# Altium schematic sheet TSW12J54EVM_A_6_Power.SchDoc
size 431 x 279 mm; Date: Not shown in title block; ApprovedBy: Not shown in title block; CheckedBy: Not shown in title block; Author: Not shown in title block; CompanyName: Not shown in title block; Engineer: Not shown in title block; Organization: Not shown in title block; Address1: Not shown in title block; Address2: Not shown in title block; Address3: Not shown in title block; Address4: Not shown in title block; DocumentNumber: 6; Revision: Use project parameter SCH_Rev; SheetNumber: 6; SheetTotal: 8; PageSetup: Record=PageOptions¦CenterHorizontal=True¦CenterVertical=True¦PrintScale=1.00¦XCorrection=1.00¦YCorrection=1.00¦PrintKind=0¦BorderSize=5000000¦LeftOffset=0¦BottomOffset=0¦Orientation=2¦PaperLength=1000¦PaperWidth=1000¦Scale=100¦PaperSource=15¦PrintQuality=600¦MediaType=1¦DitherType=10¦PaperKind=Letter¦PrintScaleMode=1
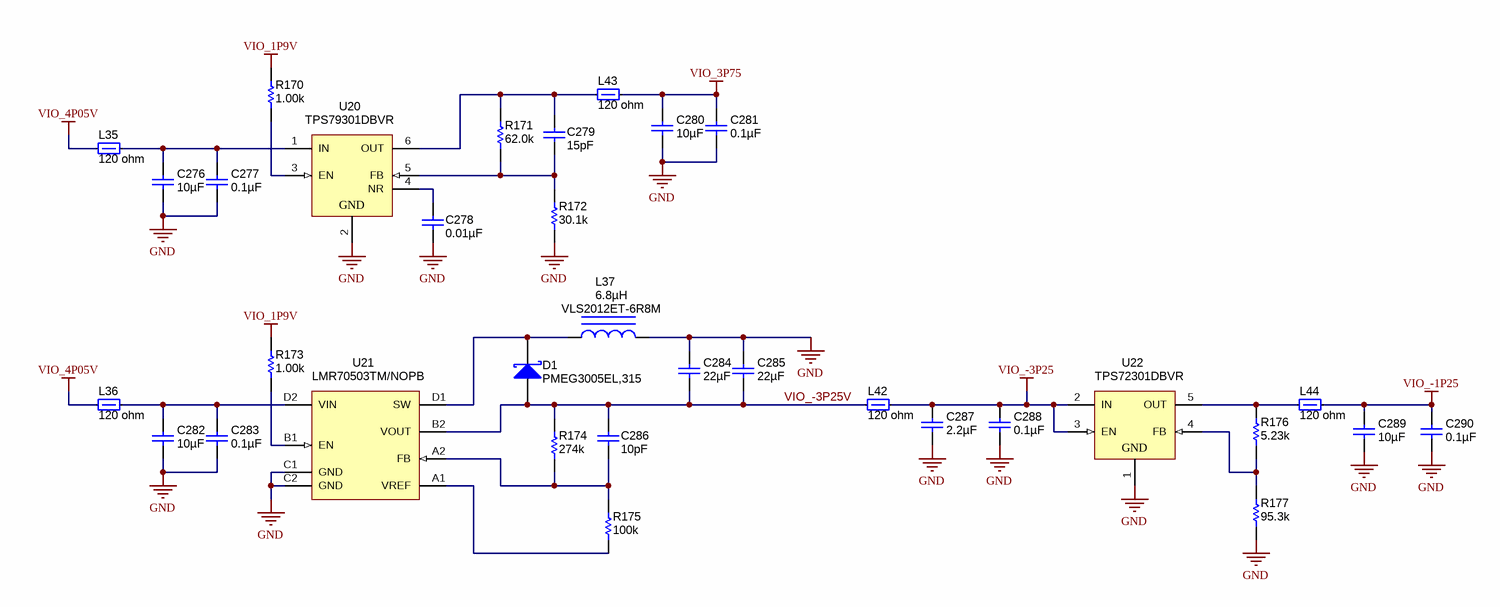
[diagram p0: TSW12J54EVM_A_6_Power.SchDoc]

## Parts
C276  ValueDisplayed: 10µF  [0603L]  (hidden comment: C1608X5R1A106M)
C277  ValueDisplayed: 0.1µF  [0603L]  (hidden comment: 06033C104JAT2A)
C278  ValueDisplayed: 0.01µF  [0603L]  (hidden comment: 06031C103MAT2A)
C279  ValueDisplayed: 15pF  [0603L]  (hidden comment: C0603C150J5GACTU)
C280  ValueDisplayed: 10µF  [0603L]  (hidden comment: C1608X5R1A106M)
C281  ValueDisplayed: 0.1µF  [0603L]  (hidden comment: 06033C104JAT2A)
C282  ValueDisplayed: 10µF  [0603L]  (hidden comment: C1608X5R1A106M)
C283  ValueDisplayed: 0.1µF  [0603L]  (hidden comment: 06033C104JAT2A)
C284  ValueDisplayed: 22µF  [0603L]  (hidden comment: C1608X5R0J226M080AC)
C285  ValueDisplayed: 22µF  [0603L]  (hidden comment: C1608X5R0J226M080AC)
C286  ValueDisplayed: 10pF  [0402L]  (hidden comment: GRM1555C1H100JA01D)
C287  ValueDisplayed: 2.2µF  [0603L]  (hidden comment: GRM188R61A225KE34D)
C288  ValueDisplayed: 0.1µF  [0603L]  (hidden comment: 06033C104JAT2A)
C289  ValueDisplayed: 10µF  [0603L]  (hidden comment: C1608X5R1A106M)
C290  ValueDisplayed: 0.1µF  [0603L]  (hidden comment: 06033C104JAT2A)
D1  PMEG3005EL,315  [SOD882]
L35  value 120 ohm  [0603]  (hidden comment: BLM18SG121TN1D)
L36  value 120 ohm  [0603]  (hidden comment: BLM18SG121TN1D)
L37  VLS2012ET-6R8M  ValueDisplayed: 6.8µH  [VLS2012]
L42  value 120 ohm  [0603]  (hidden comment: BLM18SG121TN1D)
L43  value 120 ohm  [0603]  (hidden comment: BLM18SG121TN1D)
L44  value 120 ohm  [0603]  (hidden comment: BLM18SG121TN1D)
R170  value 1.00k  [0402L]  (hidden comment: CRCW04021K00FKED)
R171  ValueDisplayed: 62.0k  [0603L]  (hidden comment: RC0603FR-0762KL)
R172  ValueDisplayed: 30.1k  [0603L]  (hidden comment: CRCW060330K1FKEA)
R173  value 1.00k  [0402L]  (hidden comment: CRCW04021K00FKED)
R174  ValueDisplayed: 274k  [0402L]  (hidden comment: CRCW0402274KFKED)
R175  ValueDisplayed: 100k  [0402L]  (hidden comment: CRCW0402100KFKED)
R176  ValueDisplayed: 5.23k  [0603L]  (hidden comment: CRCW06035K23FKEA)
R177  ValueDisplayed: 95.3k  [0603L]  (hidden comment: RC0603FR-0795K3L)
U20  TPS79301DBVR  [DBV0006A_N]
U21  LMR70503TM/NOPB  [YFX0008ADAC]
U22  TPS72301DBVR  [DBV0005A_N]

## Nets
GND: C276.2 C277.2 C278.2 C280.2 C281.2 C282.2 C283.2 C284.1 C285.1 C287.2 C288.2 C289.2 C290.2 L37.2 R172.1 R177.1 U20.2(GND) U21.C1(GND) U21.C2(GND) U22.1(GND)
VIO_1P9V: R170.1 R173.1
VIO_3P75: C280.1 C281.1 L43.2
VIO_4P05V: L35.1 L36.1
VIO_-1P25: C289.1 C290.1 L44.2
VIO_-3P25: C287.1 C288.1 L42.2 U22.2(IN) U22.3(EN)
VIO_-3P25V: C284.2 C285.2 C286.1 D1.2(A) L42.1 R174.2 U21.B2(VOUT)
NetC276_1: C276.1 C277.1 L35.2 U20.1(IN)
NetC278_1: C278.1 U20.4(NR)
NetC279_1: C279.1 L43.1 R171.1 U20.6(OUT)
NetC279_2: C279.2 R171.2 R172.2 U20.5(FB)
NetC282_1: C282.1 C283.1 L36.2 U21.D2(VIN)
NetC286_2: C286.2 R174.1 R175.2 U21.A2(FB)
NetD1_1: D1.1(K) L37.1 U21.D1(SW)
NetL44_1: L44.1 R176.2 U22.5(OUT)
NetR170_2: R170.2 U20.3(EN)
NetR173_2: R173.2 U21.B1(EN)
NetR175_1: R175.1 U21.A1(VREF)
NetR176_1: R176.1 R177.2 U22.4(FB)

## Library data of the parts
C276 C280 C282 C289 = C1608X5R1A106M: CAP, CERM, 10uF, 10V, +/-10%, C0G/NP0, 0603; Manufacturer: TDK; Polarized: N; CompType: Capacitor; U/M: EA; Cap_F: 0.00001; Tolerance_%: 10; ESR_Ohm: 0.0078; Value1: 0.0078 ohm; IRMS_A: 1.85; TaMin_C: -55; TaMax_C: 85; Cap_Case: 0603
C277 C281 C283 C288 C290 = 06033C104JAT2A: CAP, CERM, 0.1uF, 25V, +/-5%, X7R, 0603; Manufacturer: AVX; Polarized: N; CompType: Capacitor; U/M: EA; Cap_F: 0.0000001; Tolerance_%: 5; ESR_Ohm: 0.05; Value1: 0.05 ohm; VDC_V: 25; TaMin_C: -55; TaMax_C: 125; Cap_Case: 0603
C278 = 06031C103MAT2A: CAP, CERM, 0.01uF, 100V, +/-20%, X7R, 0603; Manufacturer: AVX; Polarized: N; CompType: Capacitor; U/M: EA; Cap_F: 0.00000001; Tolerance_%: 20; ESR_Ohm: 0.098; Value1: 0.098 ohm; VDC_V: 100; TaMin_C: -55; TaMax_C: 125; Cap_Case: 0603
C279 = C0603C150J5GACTU: CAP, CERM, 15 pF, 50 V, +/- 5%, C0G/NP0, 0603; Manufacturer: Kemet; Polarized: N; CompType: Capacitor; Value: 15pF; U/M: EA; Cap_F: 0.000000000015; Tolerance_%: 5; Value1: Unknown; VDC_V: 50; Value2: 50V; TaMin_C: -55; TaMax_C: 125; Cap_Case: 0603
C284 C285 = C1608X5R0J226M080AC: CAP, CERM, 22 µF, 6.3 V, +/- 20%, X5R, 0603; Manufacturer: TDK; Polarized: N; CompType: Capacitor; Value: 22uF; U/M: EA; Cap_F: 0.000022; Tolerance_%: 20; Value1: Unknown; VDC_V: 6.3; Value2: 6.3V; TaMin_C: -55; TaMax_C: 85; Cap_Case: 0603
C286 = GRM1555C1H100JA01D: CAP, CERM, 10 pF, 50 V, +/- 5%, C0G/NP0, 0402; Manufacturer: MuRata; Polarized: N; CompType: Capacitor; Value: 10pF; U/M: EA; Cap_F: 0.00000000001; Tolerance_%: 5; Value1: Unknown; VDC_V: 50; Value2: 50V; TaMin_C: -55; TaMax_C: 125; Cap_Case: 0402
C287 = GRM188R61A225KE34D: CAP, CERM, 2.2 µF, 10 V, +/- 10%, X5R, 0603; Manufacturer: MuRata; Polarized: N; CompType: Capacitor; Value: 2.2uF; U/M: EA; Cap_F: 0.0000022; Tolerance_%: 10; Value1: Unknown; Value2: 10V; TaMin_C: -55; TaMax_C: 85; Cap_Case: 0603
D1 = PMEG3005EL,315: Diode, Schottky, 30 V, 0.5 A, SOD882; Manufacturer: NXP Semiconductor; U/M: EA; Vf_V: 0.5; Value: 30V; Value1: 0.5A; Value2: 0.5V; Vr_V: 30; TJmax_C: 150
L35 L36 L42-L44 = BLM18SG121TN1D: 3A Ferrite Bead, 120 ohm @ 100MHz, SMD; Manufacturer: MuRata; Imax_A: 3; DCR_ohm: 0.025; Value1: 0.025 ohm; ZTyp@100MHz_Ohm: 120; U/M: EA
L37 = VLS2012ET-6R8M: Inductor, Shielded, Ferrite, 6.8 µH, 0.57 A, 0.498 ohm, SMD; Manufacturer: TDK; Value: 6.8uH; Ind_H: 6.8E-6; Imax_A: 0.57; Irms: 0.69A @ 40C rise; Isat: 0.57A @ 30% inductance drop; DCR_ohm: 0.498; Value2: 0.57A
R170 R173 = CRCW04021K00FKED: RES, 1.00k ohm, 1%, 0.063W, 0402; Manufacturer: Vishay-Dale; CompType: Resistor; Res_ohm: 1000; Value_Code: 1k00; Tolerance_%: 1; Power_W: 0.063; VDC_V: 50; TempCo: 100 ppm/C; EIA_Code: E96; U/M: EA
R171 = RC0603FR-0762KL: RES, 62.0 k, 1%, 0.1 W, 0603; Manufacturer: Yageo America; CompType: Resistor; Value: 62.0k; Res_ohm: 62000; Value_Code: 62k0; Tolerance_%: 1; Power_W: 0.1; Value2: 0.1W; VDC_V: 150; TempCo: 200 ppm/C; U/M: EA
R172 = CRCW060330K1FKEA: RES, 30.1 k, 1%, 0.1 W, 0603; Manufacturer: Vishay-Dale; CompType: Resistor; Value: 30.1k; Res_ohm: 30100; Value_Code: 30k1; Tolerance_%: 1; Power_W: 0.1; Value2: 0.1W; VDC_V: 75; TempCo: 100 ppm/C; EIA_Code: E96; U/M: EA
R174 = CRCW0402274KFKED: RES, 274 k, 1%, 0.063 W, 0402; Manufacturer: Vishay-Dale; CompType: Resistor; Value: 274k; Res_ohm: 274000; Tolerance_%: 1; Power_W: 0.063; Value2: 0.063W; VDC_V: 50; TempCo: 100 ppm/C; EIA_Code: E96; U/M: EA
R175 = CRCW0402100KFKED: RES, 100 k, 1%, 0.063 W, 0402; Manufacturer: Vishay-Dale; CompType: Resistor; Value: 100k; Res_ohm: 100000; Tolerance_%: 1; Power_W: 0.063; Value2: 0.063W; VDC_V: 50; TempCo: 100 ppm/C; EIA_Code: E96; U/M: EA
R176 = CRCW06035K23FKEA: RES, 5.23 k, 1%, 0.1 W, 0603; Manufacturer: Vishay-Dale; CompType: Resistor; Value: 5.23k; Res_ohm: 5230; Value_Code: 5k23; Tolerance_%: 1; Power_W: 0.1; Value2: 0.1W; VDC_V: 75; TempCo: 100 ppm/C; EIA_Code: E96; U/M: EA
R177 = RC0603FR-0795K3L: RES, 95.3 k, 1%, 0.1 W, 0603; Manufacturer: Yageo America; CompType: Resistor; Value: 95.3k; Res_ohm: 95300; Value_Code: 95k3; Tolerance_%: 1; Power_W: 0.1; Value2: 0.1W; VDC_V: 150; TempCo: 200 ppm/C; EIA_Code: E96; U/M: EA
U20 = TPS79301DBVR: Single Output High PSRR LDO, 200 mA, Adjustable 1.22 to 5.5 V Output, 2.7 to 5.5 V Input, 6-pin SOT-23 (DBV), -40 to 85 degC, Green (RoHS & no Sb/Br); Manufacturer: Texas Instruments; Alternate Manufacturer: None; Alternate PartNumber: Equivalent; Accuracy(%): 2; Iout(Max)(A): 0.2; Rating: Catalog; SubFamily: Single Channel LDO; Vdo(Typ)(mV): 77; Vin(Max)(V): 5.5; Vin(Min)(V): 2.7; Vout Adj(Min)(V): 1.22
U21 = LMR70503TM/NOPB: SIMPLE SWITCHER Buck-Boost Converter For Negative Output Voltage in uSMD, YFX0008ADAC; Manufacturer: Texas Instruments; SymbolCreator: a0411947; CompType: IC; U/M: EA
U22 = TPS72301DBVR: Single Output LDO, 200 mA, Adjustable -10 to -1.2 V Output, -10 to -2.7 V Input, 5-pin SOT-23 (DBV), -40 to 125 degC, Green (RoHS & no Sb/Br); Manufacturer: Texas Instruments; Alternate Manufacturer: None; Alternate PartNumber: Equivalent; Accuracy(%): 2; Iout(Max)(A): 0.2; Iq(Typ)(mA): 0.13; SubFamily: Single Channel LDO; Vdo(Typ)(mV): 280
